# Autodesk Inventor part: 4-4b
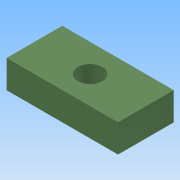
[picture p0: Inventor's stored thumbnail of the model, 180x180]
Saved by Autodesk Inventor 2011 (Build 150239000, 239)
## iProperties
Created: 2014-03
Part Number: 4-4b
Document SubType Name: Modeling
Designer: Administrator
Density: 1 g/cm^3
Author: Administrator
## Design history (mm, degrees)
sketch "草图1"
  geometry: L1 (-40, 20)-(40, 20); L2 (40, 20)-(40, -20); L3 (40, -20)-(-40, -20); L4 (-40, -20)-(-40, 20); 3 further points
  constraints: 8 end point, 2 midpoint, 2 parallel, 1 horizontal, 1 horizontal alignment, 1 perpendicular, 1 vertical alignment
  dimensions: "d0" = 80 distance of L1.start L1.end; "d1" = 40 distance of L3.end L1.start
extrude "拉伸1" new body sketch "草图1" distance "d2" = 20; taper "d3" = 0 deg
hole "Hole1" diameter "d6" = 17.6; stored, may be unused: countersink angle "d10" = 90 deg, drill point angle "d12" = 118 deg; dims "d4" = 20, "d5" = 40, "d7" = 6, "d8" = 4, "d9" = 2, "d11" = 8
node "实体1"
